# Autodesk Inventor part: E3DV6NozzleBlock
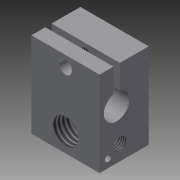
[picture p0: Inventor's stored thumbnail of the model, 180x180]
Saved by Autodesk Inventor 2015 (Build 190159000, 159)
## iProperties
Created: 2014-08
Part Number: E3DV6NozzleBlock
Material: Generic
Document SubType Name: Modeling
Designer: Jack
Density: 1 g/cm^3
Appearance: Default
Author: Jack
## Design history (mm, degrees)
sketch "Sketch1"
  geometry: L1 (0, 0)-(16, 0); L2 (16, 0)-(16, -20); L3 (16, -20)-(0, -20); L4 (0, -20)-(0, 0)
  constraints: 8 end point, 2 parallel, 1 horizontal, 1 perpendicular
  dimensions: "d0" = 16 distance of L2.end L3.end; "d1" = 20 distance of L3.end L1.start
extrude "Extrusion1" new body sketch "Sketch1" distance "d2" = 11.5; taper "d3" = 0 deg
sketch "Sketch2"
  geometry: L1 (0, 0)-(0, 20) reference; L2 (0, 20)-(-16, 20) reference; C1 r 3 at (-8, 15.5)
  constraints: 1 centre point
  dimensions: "d4" = 6 diameter of C1; "d5" = 8 distance from line of L1 C1.centre; "d6" = 4.5 distance from line of L2 C1.centre
extrude "Extrusion2" cut sketch "Sketch2" stored distance "d7" = 11.5; taper "d8" = 0 deg
sketch "Sketch3"
  geometry: L1 (0, 0)-(0, 20) reference; L2 (0, 20)-(-16, 20) reference; C1 r 1.5 at (-8, 2.5)
  constraints: 1 centre point
  dimensions: "d9" = 3 diameter of C1; "d11" = 17.5 distance from line of L2 C1.centre; "d12" = 8 distance from line of L1 C1.centre
extrude "Extrusion3" cut sketch "Sketch3" stored distance "d13" = 11.5; taper "d14" = 0 deg
sketch "Sketch4"
  geometry: L1 (20, 0)-(0, 0) reference; L2 (20, 0)-(20, 11.5) reference; L3 (0, 0)-(0, 11.5) reference; L4 (5.595, 4.75)-(0, 4.75); L5 (5.595, 3.25)-(0, 3.25); A1 r 3 centre (8.5, 4) between (5.595, 3.25) and (5.595, 4.75)
  constraints: 4 end point, 2 perpendicular, 2 point on circle, 2 point on line, 1 centre point
  dimensions: "d15" = 6 diameter of A1; "d16" = 11.5 distance from line of L2 A1.centre; "d17" = 4 distance from line of L1 A1.centre; "d18" = 1.5 distance between parallel lines of L5 L4; "d19" = 0.75 distance from line of A1.centre L4
extrude "Extrusion4" cut sketch "Sketch4" stored distance "d20" = 11.5; taper "d21" = 0 deg
sketch "Sketch5"
  geometry: L1 (20, 0)-(0, 0) reference; L2 (20, 0)-(20, 11.5) reference; C1 r 0.75 at (18, 2)
  constraints: 1 centre point
  dimensions: "d22" = 1.5 diameter of C1; "d24" = 2 distance from line of L1 C1.centre; "d25" = 2 distance from line of L2 C1.centre
extrude "Extrusion5" cut sketch "Sketch5" distance "d26" = 4.4; taper "d27" = 0 deg
sketch "Sketch6"
  geometry: L1 (20, 0)-(0, 0) reference; L2 (20, 0)-(20, 11.5) reference; C1 r 1.5 at (16.5, 4.8)
  constraints: 1 centre point
  dimensions: "d28" = 3 diameter of C1; "d29" = 4.8 distance from line of L1 C1.centre; "d30" = 3.5 distance from line of L2 C1.centre
extrude "Extrusion6" cut sketch "Sketch6" distance "d31" = 3.4; taper "d32" = 0 deg
thread "Thread1" dims "d33" = 10, "d34" = 0
thread "Thread2" dims "d35" = 10, "d36" = 0
thread "Thread3" dims "d37" = 10, "d38" = 0
body "Solid1"
